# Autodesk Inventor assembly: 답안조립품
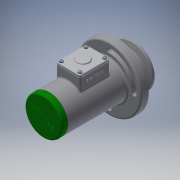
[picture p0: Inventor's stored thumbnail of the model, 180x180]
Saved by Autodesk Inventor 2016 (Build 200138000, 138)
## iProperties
Created: 2017-05
Part Number: 답안조립품
Material: 일반
Document SubType Name: Assembly
Designer: USER
Author: USER
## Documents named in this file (20)
- C:\Users\USER\Desktop\470507V1011\답안조립품.iam
- C:\Users\USER\Desktop\470507V1011\본체.ipt
- C:\Users\USER\Desktop\470507V1011\V-벨트풀리.ipt
- C:\Users\USER\Desktop\470507V1011\너트 M10.ipt
- C:\Users\USER\Desktop\470507V1011\멈춤링 15 x 1.ipt
- C:\Users\USER\Desktop\470507V1011\멈춤링 35x1.6.ipt
- C:\Users\USER\Desktop\470507V1011\베어링 15 x 35 x 11.ipt
- C:\Users\USER\Desktop\470507V1011\볼트 M4 x 10.ipt
- C:\Users\USER\Desktop\470507V1011\부시1.ipt
- C:\Users\USER\Desktop\470507V1011\부시2.ipt
- C:\Users\USER\Desktop\470507V1011\사이드 커버.ipt
- 사이드 커버.ipt
- C:\Users\USER\Desktop\470507V1011\십자볼트 M3 x 10.ipt
- C:\Users\USER\Desktop\470507V1011\오일 실 15 25 7.ipt
- C:\Users\USER\Desktop\470507V1011\와셔 3x6.ipt
- C:\Users\USER\Desktop\470507V1011\와셔 4x16.ipt
- C:\Users\USER\Desktop\470507V1011\와셔 10x21.ipt
- C:\Users\USER\Desktop\470507V1011\축.ipt
- C:\Users\USER\Desktop\470507V1011\키 4 x 4 x 18.ipt
- C:\Users\USER\Desktop\470507V1011\탑 커버.ipt
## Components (2 placed, 2 different names)
1. V-벨트풀리:1
2. ISO 4017 M4 x 10:1
